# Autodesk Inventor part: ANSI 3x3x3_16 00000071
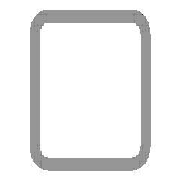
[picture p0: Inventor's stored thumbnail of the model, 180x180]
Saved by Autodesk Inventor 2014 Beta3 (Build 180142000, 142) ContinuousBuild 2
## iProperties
IsCustomPart: 1
_CCFamilyMember: 9
_CCFamilyDisplayName: ANSI AISC (Square) - Tube
_FrameMemberDoc: Frame Member File
_Version: 15.0.0
_GetPNFromCC: 1
Created: 2011-01
Part Number: ANSI 3x3x3_16 00000071
Material: Steel, Mild
Description: Tube
Document SubType Name: Modeling
Standard: ANSI
Designer: Beta-8540w
Standards Organization: ANSI
Language: en-US
Size Designation: 3x3x3/16
Categories: <MemberInstance><Categories><Category DisplayName="Structural Shapes" InternalName="089c4875-fa83-4c05-b084-43b9cc11f5ed" Mnemonic="GRDR"><CategoryParameter Dis
Stock Number: 3x3x3/16
Density: 7.86 g/cm^3
Appearance: Steel
G_W: 3.000 in
G_H: 3.000 in
G_L: 46.500 in
Author: Beta-8540w
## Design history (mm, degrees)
node "Start plane"
node "End plane"
sketch "Sketch"
  geometry: L1 (-38.1, -28.575)-(-38.1, 28.575); L2 (-28.575, 38.1)-(28.575, 38.1); L3 (38.1, 28.575)-(38.1, -28.575); L4 (28.575, -38.1)-(-28.575, -38.1); L5 (-28.575, 33.337)-(28.575, 33.338); L6 (33.338, 28.575)-(33.338, -28.575); L7 (28.575, -33.337)-(-28.575, -33.338); L8 (-33.338, -28.575)-(-33.338, 28.575); L9 (0, 56.102)-(0, -56.102) reference; L10 (-56.102, 0)-(56.102, 0) reference; A1 r 9.525 centre (-28.575, -28.575) between (-38.1, -28.575) and (-28.575, -38.1); A2 r 9.525 centre (-28.575, 28.575) between (-28.575, 38.1) and (-38.1, 28.575); A3 r 9.525 centre (28.575, 28.575) between (38.1, 28.575) and (28.575, 38.1); A4 r 9.525 centre (28.575, -28.575) between (28.575, -38.1) and (38.1, -28.575); A5 r 4.763 centre (-28.575, 28.575) between (-28.575, 33.337) and (-33.338, 28.575); A6 r 4.763 centre (28.575, 28.575) between (33.338, 28.575) and (28.575, 33.338); A7 r 4.763 centre (28.575, -28.575) between (28.575, -33.337) and (33.338, -28.575); A8 r 4.763 centre (-28.575, -28.575) between (-33.338, -28.575) and (-28.575, -33.338)
  constraints: 16 end point, 16 point on circle, 8 centre point, 8 tangent, 4 parallel, 3 equal radius, 2 perpendicular, 7 other
  dimensions: "d10" = 76.2 distance between parallel lines of L2 L4 (= G_H); "d11" = 76.2 distance between parallel lines of L1 L3 (= G_W); "d12" = 4.7625 distance between parallel lines of L3 L6 (= G_T); "d15" = 38.1 distance between parallel lines of L2 L10 (= 0.5 x d10); "d16" = 38.1 distance between parallel lines of L9 L3 (= 0.5 x d11); "d17" = 9.525 radius of A1 (= G_IR)
extrude "Body" new body sketch "Sketch" stored distance "d3" = 1181.1 (= G_L); taper "d4" = 0 deg
node "Driven Length"
  sketch "Sketch3"
    geometry: L1 (0, 0)-(10, 0) reference
    constraints: 2 end point, 1 horizontal
  workplane "Work Plane3"
  sketch "Sketch4"
    geometry: L1 (-2, 38.1)-(12, 38.1) reference; L2 (-2, 1219.2)-(12, 1219.2) reference
    dimensions: "d19" = 1181.1 distance between parallel lines of L1 L2 (derived)
workplane "Work Plane4"
split "Split1"
body "Solid1"
other parameters: "G_W" = 76.2 [user parameter; used in 1 equation term], "G_H" = 76.2 [user parameter; used in 1 equation term], "G_T" = 4.7625 [user parameter; used in 1 equation term], "G_IR" = 9.525 [user parameter; used in 1 equation term], "G_L" = 1181.1 (= d19) [user parameter; used in 1 equation term], "G_OFFSET_START" = -38.1 [user parameter; used in 1 equation term], "G_OFFSET_END" = 0 [user parameter; used in 1 equation term], "d13" = 38.1 (= -G_OFFSET_START), "d14" = 1219.2 (= G_OFFSET_END + B_L), "B_L" = 1219.2 [user parameter; used in 1 equation term], "d18" = 90 deg
